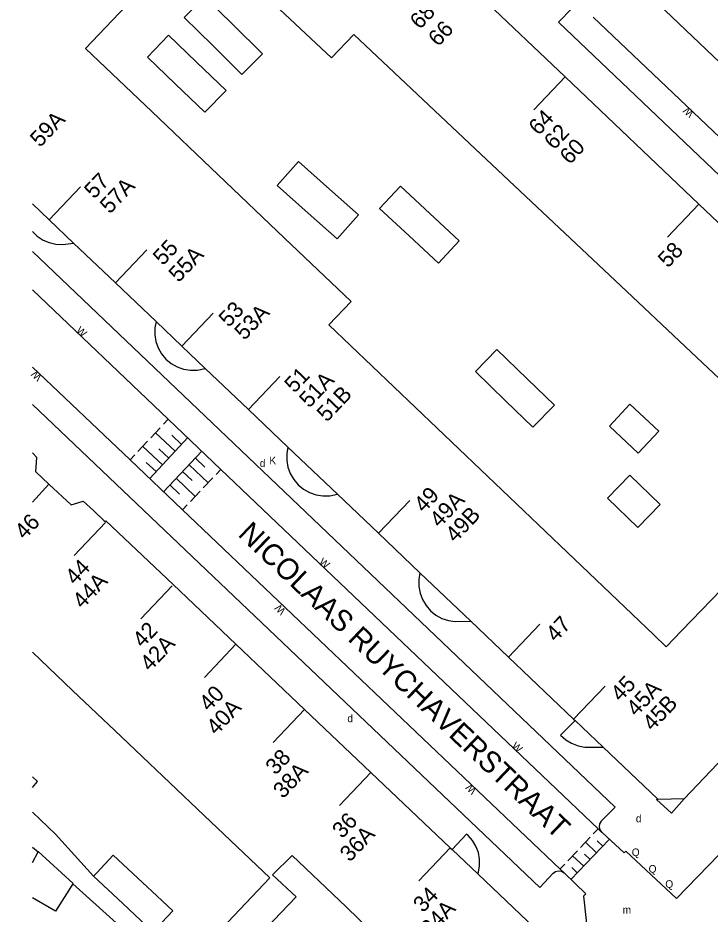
# Model space of a CAD drawing. Extents: x 134999 to 136502, y 457398 to 459002.
# Drawn here: x 134999.1 to 135044.6, y 458099.2 to 458158.3 of the extents above; entities that cross this region are included whole.
import ezdxf

# ---------------------------------------------------------------- set-up
doc = ezdxf.new("R2010")
doc.units = 0
for name, color, linetype in [('RI_DGTB_15', 7, 'Continuous'), ('RI_DGTB_2', 7, 'Continuous'), ('RI_DGTB_29', 7, 'Continuous'), ('RI_DGTB_30', 7, 'Continuous'), ('RI_DGTB_31', 7, 'Continuous'), ('RI_DGTB_35', 7, 'Continuous'), ('RI_DGTB_36', 7, 'Continuous'), ('RI_DGTB_37', 7, 'Continuous'), ('RI_DGTB_4', 7, 'Continuous'), ('RI_DGTB_43', 7, 'Continuous'), ('RI_DGTB_5', 7, 'Continuous'), ('RI_DGTB_53', 7, 'Continuous'), ('RI_DGTB_54', 7, 'Continuous'), ('RI_DGTB_6', 7, 'Continuous'), ('RI_DGTB_7', 7, 'Continuous')]:
    doc.layers.add(name, color=color, linetype=linetype)

msp = doc.modelspace()

# ---------------------------------------------------------------- linework, layer by layer
at = {"layer": 'RI_DGTB_15'}
for p, q in [((135035.083, 458154.374), (135033.022, 458152.195)), ((135001.099, 458144.967), (135003.169, 458147.139)), ((135043.889, 458145.993), (135041.828, 458143.814)), ((135005.473, 458140.802), (135007.543, 458142.974)), ((135009.848, 458136.637), (135011.918, 458138.809)), ((135014.231, 458132.464), (135016.301, 458134.636)), ((135001.097, 458127.553), (135000, 458126.356)), ((135022.796, 458124.31), (135024.866, 458126.482)), ((135004.812, 458125.03), (135002.748, 458122.854)), ((135009.21, 458120.858), (135007.146, 458118.682)), ((135031.356, 458116.159), (135033.426, 458118.331)), ((135013.409, 458116.999), (135011.345, 458114.823)), ((135035.648, 458112.074), (135037.718, 458114.246)), ((135017.934, 458112.701), (135015.87, 458110.525)), ((135022.3, 458108.554), (135020.236, 458106.378)), ((135027.524, 458103.592), (135025.46, 458101.416))]:
    msp.add_line(p, q, dxfattribs=at)
at = {"layer": 'RI_DGTB_2'}
for p, q in [((135035.083, 458154.374), (135026.387, 458162.651)), ((135029.909, 458148.939), (135021.169, 458157.169)), ((135007.865, 458152.085), (135003.498, 458156.242)), ((135043.889, 458145.993), (135035.083, 458154.374)), ((135012.239, 458147.921), (135007.865, 458152.085)), ((135038.757, 458140.604), (135029.909, 458148.939)), ((135016.613, 458143.756), (135012.239, 458147.921)), ((135000, 458146.014), (135001.099, 458144.967)), ((135048.079, 458142.004), (135043.889, 458145.993)), ((135038.757, 458140.604), (135042.987, 458136.62)), ((135019.539, 458138.039), (135028.096, 458129.876)), ((135042.987, 458136.62), (135047.125, 458132.721)), ((135028.096, 458129.876), (135036.647, 458121.717)), ((135004.03, 458125.82), (135004.733, 458125.141)), ((135046.938, 458122.219), (135042.775, 458117.899)), ((135040.929, 458117.629), (135036.647, 458121.717)), ((135009.271, 458120.929), (135013.409, 458116.999)), ((135013.409, 458116.999), (135017.934, 458112.701)), ((135031.356, 458116.159), (135035.648, 458112.074)), ((135017.934, 458112.701), (135022.3, 458108.554)), ((135042.942, 458106.829), (135048.385, 458112.559)), ((135022.3, 458108.554), (135027.524, 458103.592))]:
    msp.add_line(p, q, dxfattribs=at)
for points in [[(135002.217, 458163.676), (135006.59, 458159.51), (135003.498, 458156.242)], [(135015.275, 458159.804), (135019.709, 458155.619), (135021.169, 458157.169)], [(135001.099, 458144.967), (135002.714, 458143.429)], [(135016.613, 458143.756), (135021, 458139.58), (135019.539, 458138.039)], [(135002.714, 458143.429), (135005.473, 458140.802)], [(135005.473, 458140.802), (135008.146, 458138.258)], [(135008.146, 458138.258), (135009.848, 458136.637)], [(135009.848, 458136.637), (135011.389, 458135.169)], [(135011.389, 458135.169), (135014.231, 458132.464)], [(135016.827, 458129.993), (135014.231, 458132.464)], [(135020.089, 458126.888), (135016.827, 458129.993)], [(135022.796, 458124.31), (135020.089, 458126.888)], [(135004.733, 458125.141), (135004.8, 458125.08), (135004.85, 458125.13), (135009.271, 458120.929)], [(135022.796, 458124.31), (135025.53, 458121.707)], [(135025.53, 458121.707), (135028.877, 458118.52)], [(135028.877, 458118.52), (135031.356, 458116.159)], [(135042.775, 458117.899), (135041.756, 458116.842), (135040.929, 458117.629)], [(135035.648, 458112.074), (135035.748, 458111.978)], [(135035.748, 458111.978), (135037.594, 458110.222)], [(135037.594, 458110.222), (135041.169, 458106.819)], [(135042.942, 458106.829), (135042.09, 458105.87), (135041.12, 458106.78), (135041.169, 458106.819)], [(135042.942, 458106.829), (135041.22, 458106.77), (135041.169, 458106.819)], [(135027.524, 458103.592), (135027.642, 458103.48)], [(135027.642, 458103.48), (135029.36, 458101.849)], [(135029.36, 458101.849), (135033.069, 458098.328)]]:
    msp.add_lwpolyline(points, dxfattribs=at)
at = {"layer": 'RI_DGTB_31'}
for p, q in [((135008.631, 458131.491), (135008.945, 458131.827)), ((135007.795, 458130.595), (135008.422, 458131.267)), ((135009.41, 458129.715), (135008.108, 458130.931)), ((135009.828, 458130.163), (135009.178, 458130.771)), ((135006.958, 458129.7), (135007.585, 458130.372)), ((135007.737, 458127.924), (135010.247, 458130.611)), ((135008.573, 458128.82), (135007.272, 458130.036)), ((135008.992, 458129.268), (135008.341, 458129.876)), ((135011.167, 458129.711), (135008.633, 458127.052)), ((135006.435, 458129.14), (135006.749, 458129.476)), ((135008.155, 458128.372), (135007.504, 458128.98)), ((135010.745, 458129.268), (135011.371, 458128.671)), ((135009.9, 458128.382), (135010.527, 458127.785)), ((135010.322, 458128.825), (135011.575, 458127.631)), ((135012.42, 458128.517), (135012.103, 458128.185)), ((135009.478, 458127.938), (135010.731, 458126.744)), ((135011.892, 458127.963), (135011.259, 458127.298)), ((135009.055, 458127.495), (135009.682, 458126.898)), ((135011.047, 458127.077), (135010.414, 458126.412)), ((135010.203, 458126.19), (135009.886, 458125.858)), ((135036.946, 458104.509), (135037.26, 458104.84)), ((135036.11, 458103.625), (135036.737, 458104.288)), ((135035.476, 458101.502), (135037.986, 458104.152)), ((135037.149, 458103.269), (135036.423, 458103.957)), ((135037.568, 458103.711), (135037.205, 458104.054)), ((135035.273, 458102.742), (135035.9, 458103.405)), ((135036.313, 458102.386), (135035.587, 458103.073)), ((135036.731, 458102.827), (135036.368, 458103.171)), ((135034.75, 458102.19), (135035.064, 458102.521)), ((135035.894, 458101.944), (135035.531, 458102.288))]:
    msp.add_line(p, q, dxfattribs=at)
at = {"layer": 'RI_DGTB_4'}
for points in [[(135001.097, 458127.553), (135000.226, 458128.361), (135000.296, 458129.311), (135000, 458129.603)], [(135001.097, 458127.553), (135002.562, 458126.195), (135003.354, 458126.431), (135004.03, 458125.82)]]:
    msp.add_lwpolyline(points, dxfattribs=at)
at = {"layer": 'RI_DGTB_5'}
for p, q in [((135002.654, 458113.961), (135000, 458116.484)), ((135005.431, 458111.323), (135002.654, 458113.961)), ((135006.79, 458110.031), (135005.431, 458111.323)), ((135011.315, 458105.732), (135006.79, 458110.031)), ((135015.639, 458101.623), (135011.315, 458105.732)), ((135017.119, 458103.098), (135015.821, 458101.815))]:
    msp.add_line(p, q, dxfattribs=at)
for points in [[(135020.659, 458099.707), (135017.119, 458103.098)], [(135022.322, 458098.114), (135020.659, 458099.707)]]:
    msp.add_lwpolyline(points, dxfattribs=at)
at = {"layer": 'RI_DGTB_53'}
for p, q in [((135000, 458105.938), (135001.535, 458104.498)), ((135004.03, 458101.73), (135001.535, 458104.498)), ((135037.497, 458104.632), (135037.52, 458104.61)), ((135037.52, 458104.61), (135038.98, 458103.27)), ((135035.02, 458101.95), (135036.45, 458100.56))]:
    msp.add_line(p, q, dxfattribs=at)
for points in [[(135064.523, 458131.819), (135064.507, 458131.822), (135064.317, 458131.777), (135064.16, 458131.66), (135063.28, 458130.72), (135034.66, 458157.97), (135035.55, 458158.89), (135035.614, 458158.948), (135035.703, 458159.105), (135035.716, 458159.286), (135035.651, 458159.455), (135034.81, 458160.26), (135034.781, 458160.292), (135034.62, 458160.399), (135034.431, 458160.433), (135034.243, 458160.387), (135034.09, 458160.27), (135033.2, 458159.34), (135010.54, 458180.9), (135011.446, 458181.826), (135011.55, 458181.995), (135011.58, 458182.191), (135011.531, 458182.383), (135011.41, 458182.54)], [(135039.405, 458160.948), (135067.075, 458134.579)], [(135036.935, 458158.316), (135064.629, 458132.012)], [(135000, 458142.877), (135038.39, 458106.28), (135037.46, 458105.34), (135037.358, 458105.169), (135037.33, 458104.972), (135037.382, 458104.78), (135037.497, 458104.632)], [(135000, 458140.347), (135008.945, 458131.827)], [(135000, 458135.262), (135006.435, 458129.14)], [(135000, 458132.786), (135033.43, 458100.98), (135034.3, 458101.93), (135034.463, 458102.046), (135034.659, 458102.09), (135034.856, 458102.055), (135035.02, 458101.95)], [(135008.945, 458131.827), (135012.42, 458128.517)], [(135006.435, 458129.14), (135009.886, 458125.858)], [(135012.42, 458128.517), (135037.268, 458104.85)], [(135009.886, 458125.858), (135034.758, 458102.199)], [(135037.268, 458104.85), (135037.497, 458104.632)], [(135037.52, 458104.61), (135037.504, 458104.623), (135037.497, 458104.632)], [(135034.758, 458102.199), (135035.02, 458101.95)]]:
    msp.add_lwpolyline(points, dxfattribs=at)
at = {"layer": 'RI_DGTB_54'}
for p, q in [((135000, 458103.647), (135000.373, 458103.326)), ((135002.677, 458101.219), (135006.805, 458097.5))]:
    msp.add_line(p, q, dxfattribs=at)
for points in [[(135045.45, 458102.95), (135045.24, 458103.15), (135042.43, 458100.249), (135039.1, 458103.38), (135038.98, 458103.27)], [(135036.45, 458100.56), (135036.3, 458100.4), (135036.96, 458094.4), (135035.82, 458093.12), (135035.95, 458093.01)]]:
    msp.add_lwpolyline(points, dxfattribs=at)
at = {"layer": 'RI_DGTB_6'}
for p, q in [((135000, 458102.622), (135000.373, 458103.326)), ((135007.246, 458101.319), (135008.204, 458100.422)), ((135010.433, 458096.142), (135015.639, 458101.623))]:
    msp.add_line(p, q, dxfattribs=at)
for points in [[(135011.88, 458156.431), (135010.006, 458158.294), (135011.36, 458159.657), (135013.235, 458157.795)], [(135013.235, 458157.795), (135015.156, 458155.886), (135013.793, 458154.531), (135011.88, 458156.431)], [(135009.439, 458153.899), (135007.586, 458155.673), (135008.965, 458157.113), (135010.818, 458155.34)], [(135010.818, 458155.34), (135012.763, 458153.478), (135011.368, 458152.052), (135009.439, 458153.899)], [(135018.168, 458145.393), (135016.116, 458147.212), (135017.522, 458148.797), (135019.574, 458146.979)], [(135019.574, 458146.979), (135021.49, 458145.281), (135020.076, 458143.702), (135018.168, 458145.393)], [(135024.811, 458143.902), (135022.87, 458145.709), (135024.241, 458147.181), (135026.181, 458145.374)], [(135026.181, 458145.374), (135028.122, 458143.567), (135026.752, 458142.095)], [(135026.752, 458142.095), (135024.811, 458143.902)], [(135031.172, 458133.037), (135029.188, 458134.966), (135030.602, 458136.422), (135032.587, 458134.493)], [(135032.587, 458134.493), (135034.384, 458132.747), (135032.964, 458131.296), (135031.172, 458133.037)], [(135039.904, 458129.592), (135038.007, 458131.366), (135039.361, 458132.814), (135041.258, 458131.04), (135039.904, 458129.592)], [(135039.887, 458124.696), (135037.881, 458126.625), (135039.344, 458128.148), (135041.351, 458126.219), (135039.887, 458124.696)], [(135000, 458107.574), (135000.348, 458107.964), (135000, 458108.276)], [(135002.677, 458101.219), (135002.691, 458101.241), (135000.391, 458103.361), (135000.373, 458103.326)], [(135004.241, 458101.956), (135005.327, 458103.116), (135007.246, 458101.319)], [(135004.03, 458101.73), (135004.241, 458101.956)], [(135015.391, 458098.297), (135017.387, 458100.365), (135015.821, 458101.815)], [(135005.95, 458099.934), (135004.03, 458101.73)], [(135002.677, 458101.219), (135001.531, 458099.421), (135000, 458100.307)], [(135008.204, 458100.422), (135009.247, 458099.446), (135008.151, 458098.283)], [(135007.946, 458098.066), (135005.95, 458099.934)]]:
    msp.add_lwpolyline(points, dxfattribs=at)
at = {"layer": 'RI_DGTB_7'}
for p, q in [((135035.748, 458111.978), (135034.78, 458111.01)), ((135028.6, 458104.5), (135027.642, 458103.48))]:
    msp.add_line(p, q, dxfattribs=at)
for points in [[(135000, 458144.185), (135000.327, 458143.876), (135000.704, 458143.63), (135001.118, 458143.455), (135001.557, 458143.355), (135002.007, 458143.335), (135002.714, 458143.429)], [(135008.146, 458138.258), (135008.066, 458137.838), (135008.061, 458137.388), (135008.136, 458136.944), (135008.288, 458136.521), (135008.513, 458136.131), (135008.803, 458135.787), (135009.149, 458135.499), (135009.541, 458135.277), (135009.965, 458135.128), (135010.409, 458135.057), (135010.859, 458135.065), (135011.389, 458135.169)], [(135016.827, 458129.993), (135016.751, 458129.564), (135016.752, 458129.111), (135016.832, 458128.665), (135016.989, 458128.241), (135017.219, 458127.85), (135017.513, 458127.506), (135017.863, 458127.219), (135018.259, 458126.998), (135018.687, 458126.849), (135019.134, 458126.779), (135019.587, 458126.787), (135020.089, 458126.888)], [(135025.53, 458121.707), (135025.454, 458121.264), (135025.457, 458120.811), (135025.54, 458120.366), (135025.7, 458119.942), (135025.931, 458119.553), (135026.228, 458119.211), (135026.58, 458118.926), (135026.976, 458118.708), (135027.405, 458118.562), (135027.852, 458118.495), (135028.877, 458118.52)], [(135034.78, 458111.01), (135035.127, 458110.712), (135035.521, 458110.479), (135035.949, 458110.319), (135036.398, 458110.235), (135037.594, 458110.222)], [(135029.36, 458101.849), (135029.459, 458102.398), (135029.458, 458102.843), (135029.377, 458103.28), (135029.22, 458103.697), (135028.991, 458104.078), (135028.697, 458104.412), (135028.6, 458104.5)]]:
    msp.add_lwpolyline(points, dxfattribs=at)

# ---------------------------------------------------------------- texts
at = {"layer": 'RI_DGTB_29'}
for p in [(135014.98, 458128.68), (135020.75, 458111.87), (135039.75, 458105.28)]:
    msp.add_text('d', height=0.5, rotation=359.99963, dxfattribs=at).set_placement(p)
at = {"layer": 'RI_DGTB_30'}
for s, rotation, p in [('W', 137.2894, (135043.614, 458152.015)), ('W', 318.36594, (135002.842, 458137.614)), ('W', 137.2014, (135000.673, 458134.655)), ('K', 359.99963, (135015.61, 458128.86)), ('W', 322.12451, (135018.84, 458122.336)), ('W', 134.99879, (135016.724, 458119.241)), ('W', 317.2901, (135031.528, 458110.246)), ('W', 134.99879, (135029.294, 458107.411))]:
    msp.add_text(s, height=0.5, rotation=rotation, dxfattribs=at).set_placement(p)
at = {"layer": 'RI_DGTB_31'}
for p in [(135039.48, 458103.05), (135040.59, 458101.96), (135041.69, 458100.96)]:
    msp.add_text('Q', height=0.5, rotation=359.99963, dxfattribs=at).set_placement(p)
at = {"layer": 'RI_DGTB_35'}
for s, rotation, p in [('45', 46.3748, (135038.739, 458113.171)), ('34', 46.5134, (135025.738, 458099.273))]:
    msp.add_text(s, height=1.054, rotation=rotation, dxfattribs=at).set_placement(p)
at = {"layer": 'RI_DGTB_36'}
for s, rotation, p in [('68', 46.6026, (135025.528, 458157.449)), ('66', 46.5947, (135026.732, 458156.317)), ('64', 46.6026, (135033.348, 458150.465)), ('59A', 46.3829, (135000.505, 458149.686)), ('62', 46.5947, (135034.363, 458149.515)), ('60', 46.6026, (135035.397, 458148.549)), ('57', 46.3749, (135004.068, 458146.289)), ('57A', 46.3829, (135005.104, 458145.303)), ('55', 46.3829, (135008.598, 458141.899)), ('58', 46.6026, (135041.863, 458141.742)), ('55A', 46.3748, (135009.634, 458140.782)), ('53', 46.3829, (135012.929, 458137.829)), ('53A', 46.3748, (135013.966, 458136.974)), ('51', 46.3829, (135017.26, 458133.501)), ('51A', 46.3748, (135018.232, 458132.516)), ('51B', 46.3829, (135019.394, 458131.592)), ('49', 46.3829, (135025.785, 458125.613)), ('49A', 46.3749, (135026.82, 458124.627)), ('49B', 46.3829, (135027.855, 458123.641)), ('46', 46.3912, (134999.485, 458123.845)), ('44', 46.5134, (135002.814, 458120.846)), ('44A', 46.5134, (135003.302, 458119.282)), ('42', 46.5134, (135007.253, 458116.717)), ('47', 46.3829, (135034.471, 458117.096)), ('42A', 46.5134, (135007.751, 458115.162)), ('40', 46.5134, (135011.636, 458112.527)), ('45A', 46.3829, (135039.777, 458112.192)), ('45B', 46.3748, (135040.839, 458111.232)), ('40A', 46.5134, (135012.115, 458110.955)), ('38', 46.5134, (135016.015, 458108.338)), ('38A', 46.5134, (135016.513, 458106.783)), ('36', 46.5134, (135020.408, 458104.158)), ('36A', 46.5134, (135020.911, 458102.61)), ('34A', 46.5134, (135026.227, 458097.711))]:
    msp.add_text(s, height=1.054, rotation=rotation, dxfattribs=at).set_placement(p)
at = {"layer": 'RI_DGTB_37'}
msp.add_text('NICOLAAS RUYCHAVERSTRAAT', height=1.4, rotation=316.41643, dxfattribs=at).set_placement((135013.482, 458124.181))
at = {"layer": 'RI_DGTB_43'}
msp.add_text('m', height=0.5, dxfattribs=at).set_placement((135038.878, 458099.264))

doc.saveas('drawing.dxf')
